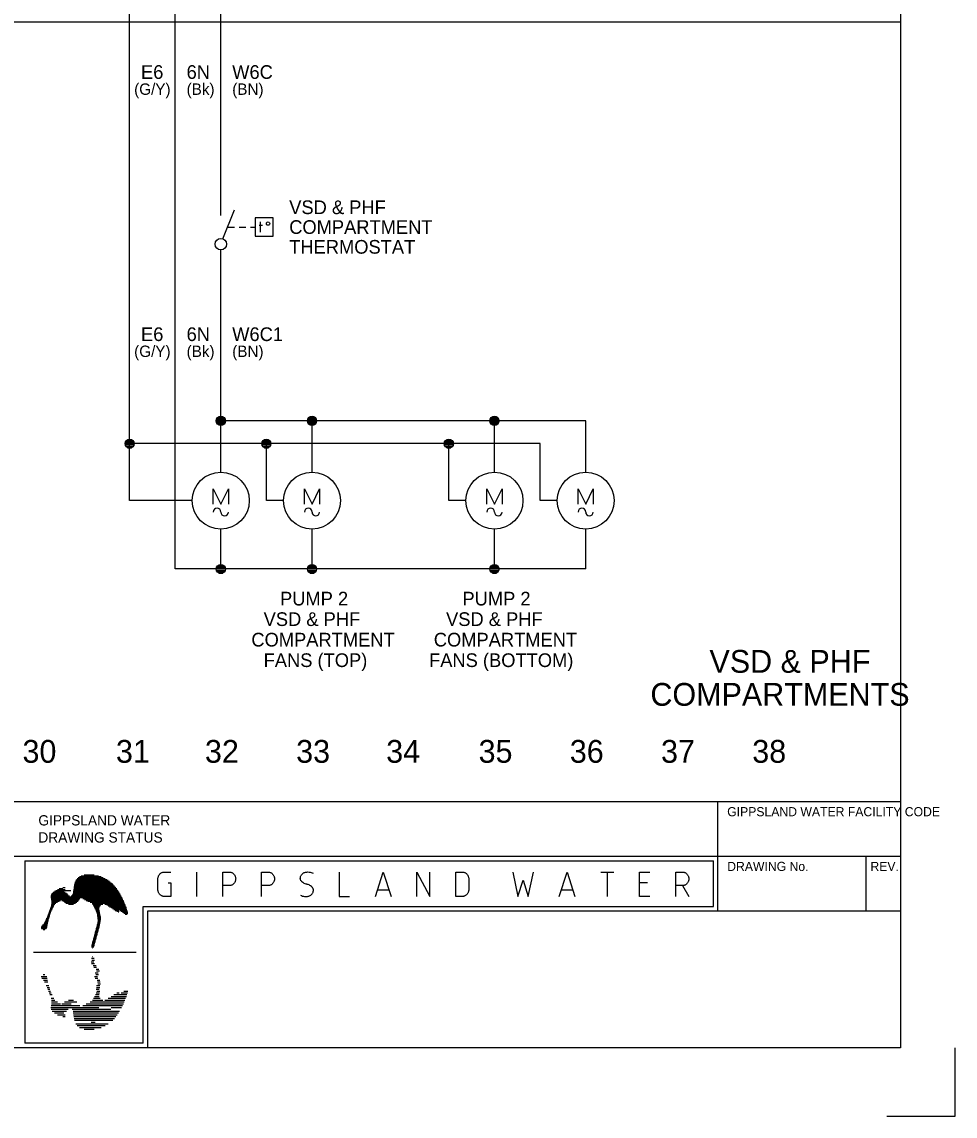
# Model space of a CAD drawing. Extents: x 0 to 841, y 0 to 594.
# Drawn here: x 636.4 to 841, y 0 to 240 of the extents above; entities that cross this region are included whole.
import ezdxf

# ---------------------------------------------------------------- set-up
doc = ezdxf.new("R2010")
doc.units = 0
for name, color, linetype in [('A1BORDER', 7, 'Continuous'), ('Level 1', 7, 'Continuous'), ('Level 10', 7, 'Continuous')]:
    doc.layers.add(name, color=color, linetype=linetype)

msp = doc.modelspace()

# ---------------------------------------------------------------- linework, layer by layer
at = {"layer": 'A1BORDER'}
for p, q in [((829, 581), (829, 15)), ((592.5, 69), (829, 69)), ((789, 45), (789, 69)), ((28, 57), (829, 57)), ((637, 56), (788, 56)), ((637, 56), (637, 16)), ((788, 46), (788, 56)), ((821.5, 45), (821.5, 57)), ((650.01, 52.92), (652.2, 52.92)), ((647.85, 50.52), (656.69, 50.52)), ((647.88, 50.72), (656.5, 50.72)), ((647.91, 50.92), (656.3, 50.92)), ((647.96, 51.12), (656.08, 51.12)), ((648.03, 51.32), (655.85, 51.32)), ((648.12, 51.52), (655.59, 51.52)), ((648.23, 51.72), (655.31, 51.72)), ((648.37, 51.92), (655, 51.92)), ((648.53, 52.12), (654.64, 52.12)), ((648.74, 52.32), (654.24, 52.32)), ((649.02, 52.52), (653.76, 52.52)), ((649.39, 52.72), (653.15, 52.72)), ((642.73, 48.12), (658.25, 48.12)), ((642.75, 48.32), (646.79, 48.32)), ((642.81, 48.52), (646.55, 48.52)), ((642.9, 48.72), (646.37, 48.72)), ((643.04, 48.92), (646.16, 48.92)), ((643.26, 49.12), (645.9, 49.12)), ((643.54, 49.32), (645.57, 49.32)), ((643.85, 49.52), (647.09, 49.52)), ((644.18, 49.72), (645.89, 49.72)), ((644.54, 49.92), (645.36, 49.92)), ((645.37, 50.12), (645.86, 50.12)), ((647.19, 48.32), (658.14, 48.32)), ((647.42, 48.52), (658.03, 48.52)), ((647.54, 48.72), (657.92, 48.72)), ((647.61, 48.92), (657.8, 48.92)), ((647.63, 49.12), (657.68, 49.12)), ((647.66, 49.32), (657.57, 49.32)), ((647.69, 49.52), (657.44, 49.52)), ((647.71, 49.72), (657.31, 49.72)), ((647.75, 49.92), (657.17, 49.92)), ((647.78, 50.12), (657.02, 50.12)), ((647.81, 50.32), (656.86, 50.32)), ((642.65, 45.72), (643.2, 45.72)), ((642.72, 45.92), (643.3, 45.92)), ((642.74, 47.92), (658.35, 47.92)), ((642.79, 47.72), (649.08, 47.72)), ((642.79, 46.12), (643.4, 46.12)), ((642.83, 47.52), (648.95, 47.52)), ((642.84, 46.32), (643.5, 46.32)), ((642.85, 47.31), (644.88, 47.31)), ((642.87, 47.12), (644.57, 47.12)), ((642.87, 46.52), (643.6, 46.52)), ((642.88, 46.92), (644.23, 46.92)), ((642.88, 46.72), (643.83, 46.72)), ((645.14, 47.31), (648.83, 47.31)), ((645.49, 47.12), (648.67, 47.12)), ((645.76, 46.92), (648.42, 46.92)), ((646.05, 46.72), (648.11, 46.72)), ((646.62, 46.52), (647.67, 46.52)), ((649.72, 47.72), (658.45, 47.72)), ((650.12, 47.52), (658.55, 47.52)), ((650.48, 47.31), (658.64, 47.31)), ((650.87, 47.12), (658.73, 47.12)), ((651.36, 46.92), (658.82, 46.92)), ((651.76, 46.72), (658.9, 46.72)), ((651.88, 46.52), (654.15, 46.52)), ((651.99, 46.32), (653.71, 46.32)), ((652.1, 46.12), (653.52, 46.12)), ((652.2, 45.92), (653.4, 45.92)), ((652.31, 45.72), (653.33, 45.72)), ((654.57, 46.52), (658.99, 46.52)), ((655, 46.32), (659.07, 46.32)), ((655.31, 46.12), (659.14, 46.12)), ((655.62, 45.92), (659.22, 45.92)), ((655.93, 45.72), (659.29, 45.72)), ((663, 46), (788, 46)), ((663, 16), (663, 46)), ((641.73, 43.32), (642.3, 43.32)), ((641.82, 43.51), (642.35, 43.51)), ((641.91, 43.72), (642.41, 43.72)), ((641.99, 43.92), (642.48, 43.92)), ((642.06, 44.12), (642.55, 44.12)), ((642.13, 44.32), (642.62, 44.32)), ((642.21, 44.52), (642.69, 44.52)), ((642.28, 44.72), (642.76, 44.72)), ((642.35, 44.92), (642.83, 44.92)), ((642.43, 45.12), (642.9, 45.12)), ((642.5, 45.32), (643, 45.32)), ((642.57, 45.52), (643.1, 45.52)), ((652.41, 45.52), (653.31, 45.52)), ((652.5, 45.32), (653.34, 45.32)), ((652.6, 45.12), (653.38, 45.12)), ((652.69, 44.92), (653.41, 44.92)), ((652.78, 44.72), (653.44, 44.72)), ((652.83, 44.52), (653.48, 44.52)), ((652.86, 44.32), (653.53, 44.32)), ((652.89, 44.12), (653.57, 44.12)), ((652.91, 43.92), (653.62, 43.92)), ((652.94, 43.72), (653.67, 43.72)), ((652.97, 43.51), (653.71, 43.51)), ((653, 43.32), (653.69, 43.32)), ((656.24, 45.52), (659.35, 45.52)), ((656.55, 45.32), (659.42, 45.32)), ((656.86, 45.12), (657.74, 45.12)), ((657.17, 44.92), (657.68, 44.92)), ((657.51, 44.72), (657.54, 44.72)), ((657.91, 45.12), (659.48, 45.12)), ((658.19, 44.92), (659.54, 44.92)), ((658.47, 44.72), (659.59, 44.72)), ((658.75, 44.52), (659.58, 44.52)), ((659.02, 44.32), (659.47, 44.32)), ((664, 45), (829, 45)), ((664, 15), (664, 45)), ((640.62, 41.32), (641.88, 41.32)), ((640.63, 41.52), (641.93, 41.52)), ((640.72, 41.12), (641.73, 41.12)), ((640.73, 41.72), (641.95, 41.72)), ((640.9, 41.92), (641.97, 41.92)), ((641.03, 40.92), (641.43, 40.92)), ((641.1, 42.12), (642, 42.12)), ((641.25, 42.31), (642.04, 42.31)), ((641.37, 42.52), (642.09, 42.52)), ((641.46, 42.72), (642.15, 42.72)), ((641.55, 42.92), (642.2, 42.92)), ((641.64, 43.12), (642.25, 43.12)), ((652.57, 40.92), (653.2, 40.92)), ((652.63, 41.12), (653.26, 41.12)), ((652.68, 41.32), (653.31, 41.32)), ((652.74, 41.52), (653.37, 41.52)), ((652.79, 41.72), (653.41, 41.72)), ((652.85, 41.92), (653.45, 41.92)), ((652.9, 42.12), (653.49, 42.12)), ((652.95, 42.31), (653.53, 42.31)), ((652.99, 42.52), (653.57, 42.52)), ((653.02, 43.12), (653.67, 43.12)), ((653.03, 42.72), (653.61, 42.72)), ((653.05, 42.92), (653.64, 42.92)), ((651.92, 38.52), (652.55, 38.52)), ((651.98, 38.72), (652.61, 38.72)), ((652.03, 38.92), (652.66, 38.92)), ((652.09, 39.12), (652.72, 39.12)), ((652.14, 39.32), (652.77, 39.32)), ((652.2, 39.52), (652.82, 39.52)), ((652.25, 39.72), (652.88, 39.72)), ((652.3, 39.92), (652.93, 39.92)), ((652.36, 40.12), (652.99, 40.12)), ((652.41, 40.32), (653.04, 40.32)), ((652.47, 40.52), (653.1, 40.52)), ((652.52, 40.72), (653.15, 40.72)), ((651.63, 37.32), (652.23, 37.32)), ((651.64, 37.12), (652.17, 37.12)), ((651.65, 37.52), (652.28, 37.52)), ((651.71, 37.72), (652.34, 37.72)), ((651.76, 37.92), (652.39, 37.92)), ((651.79, 36.92), (651.9, 36.92)), ((651.82, 38.12), (652.44, 38.12)), ((651.87, 38.32), (652.5, 38.32)), ((638.93, 35.98), (661.47, 35.98)), ((651.54, 33.84), (652.17, 33.84)), ((651.63, 34.64), (652.23, 34.64)), ((651.71, 34.24), (652.34, 34.24)), ((651.79, 35.04), (651.9, 35.04)), ((651.65, 33.44), (652.28, 33.44)), ((652.03, 33.04), (652.66, 33.04)), ((652.14, 32.64), (652.77, 32.64)), ((652.47, 31.44), (653.1, 31.44)), ((652.66, 32.24), (653.29, 32.24)), ((652.77, 31.84), (653.4, 31.84)), ((640.62, 30.64), (641.88, 30.64)), ((640.73, 30.24), (641.95, 30.24)), ((641.03, 31.04), (641.43, 31.04)), ((641.1, 29.84), (642, 29.84)), ((641.37, 29.44), (642.09, 29.44)), ((652.34, 30.64), (652.97, 30.64)), ((652.45, 30.24), (653.07, 30.24)), ((652.57, 31.04), (653.2, 31.04)), ((652.9, 29.84), (653.49, 29.84)), ((652.99, 29.44), (653.57, 29.44)), ((653.05, 29.04), (653.64, 29.04)), ((641.73, 28.64), (642.3, 28.64)), ((641.91, 28.24), (642.41, 28.24)), ((642.06, 27.84), (642.55, 27.84)), ((642.21, 27.44), (642.69, 27.44)), ((642.35, 27.04), (642.83, 27.04)), ((642.5, 26.64), (643, 26.64)), ((652.5, 26.64), (653.34, 26.64)), ((652.66, 27.84), (653.35, 27.84)), ((652.69, 27.04), (653.41, 27.04)), ((652.72, 28.24), (653.44, 28.24)), ((652.77, 28.64), (653.46, 28.64)), ((652.83, 27.44), (653.48, 27.44)), ((656.55, 26.64), (659.42, 26.64)), ((657.17, 27.04), (657.68, 27.04)), ((658.19, 27.04), (659.54, 27.04)), ((658.75, 27.44), (659.58, 27.44)), ((642.79, 25.84), (643.4, 25.84)), ((642.79, 24.24), (649.08, 24.24)), ((642.85, 24.65), (644.88, 24.65)), ((642.87, 25.44), (643.6, 25.44)), ((642.88, 25.04), (644.23, 25.04)), ((645.14, 24.65), (647.18, 24.65)), ((645.76, 25.04), (648.42, 25.04)), ((646.62, 25.44), (647.67, 25.44)), ((649.72, 24.24), (658.45, 24.24)), ((650.48, 24.65), (658.64, 24.65)), ((651.36, 25.04), (658.82, 25.04)), ((651.88, 25.44), (654.15, 25.44)), ((652.1, 25.84), (653.52, 25.84)), ((652.31, 26.24), (653.33, 26.24)), ((654.57, 25.44), (658.99, 25.44)), ((655.31, 25.84), (659.14, 25.84)), ((655.93, 26.24), (659.29, 26.24)), ((642.73, 23.84), (653.27, 23.84)), ((642.81, 23.44), (646.55, 23.44)), ((643.04, 23.04), (646.16, 23.04)), ((643.54, 22.64), (645.57, 22.64)), ((644.18, 22.24), (645.89, 22.24)), ((645.37, 21.84), (645.86, 21.84)), ((647.42, 23.44), (655.89, 23.44)), ((647.61, 23.04), (657.8, 23.04)), ((647.66, 22.64), (657.57, 22.64)), ((647.71, 22.24), (657.31, 22.24)), ((647.78, 21.84), (657.02, 21.84)), ((655.94, 23.84), (658.25, 23.84)), ((647.85, 21.44), (656.69, 21.44)), ((647.91, 21.04), (656.3, 21.04)), ((648.23, 20.24), (655.31, 20.24)), ((648.53, 19.84), (654.64, 19.84)), ((649.02, 19.44), (653.76, 19.44)), ((651.57, 20.64), (652.44, 20.64)), ((650.01, 19.04), (652.2, 19.04)), ((829, 15), (28, 15)), ((663, 16), (637, 16)), ((829, 15), (829, 15)), ((841, 0), (841, 15)), ((826, 0), (841, 0))]:
    msp.add_line(p, q, dxfattribs=at)
for points in [[(668.49, 51.15), (669.06, 51.15), (669.06, 48.16), (667.64, 48.16), (667.51, 48.16), (667.39, 48.18), (667.28, 48.21), (667.15, 48.25), (667.04, 48.3), (666.93, 48.36), (666.82, 48.43), (666.73, 48.51), (666.64, 48.6), (666.55, 48.7), (666.48, 48.8), (666.41, 48.91), (666.35, 49.02), (666.31, 49.14), (666.27, 49.27), (666.24, 49.39), (666.22, 49.52), (666.22, 49.66), (666.22, 52.05), (666.22, 52.18), (666.24, 52.31), (666.27, 52.43), (666.31, 52.56), (666.35, 52.67), (666.41, 52.79), (666.48, 52.9), (666.55, 53), (666.64, 53.1), (666.73, 53.19), (666.82, 53.27), (666.93, 53.34), (667.04, 53.4), (667.15, 53.45), (667.28, 53.49), (667.39, 53.52), (667.51, 53.54), (667.64, 53.54), (669.06, 53.54)], [(674.74, 48.16), (674.74, 53.54)], [(680.42, 48.16), (680.42, 53.54), (681.84, 53.54), (681.96, 53.54), (682.08, 53.52), (682.2, 53.49), (682.32, 53.45), (682.43, 53.4), (682.54, 53.34), (682.65, 53.27), (682.74, 53.19), (682.84, 53.1), (682.92, 53), (682.99, 52.9), (683.06, 52.79), (683.12, 52.67), (683.17, 52.56), (683.21, 52.43), (683.23, 52.31), (683.25, 52.18), (683.26, 52.05), (683.25, 51.91), (683.23, 51.78), (683.21, 51.66), (683.17, 51.53), (683.12, 51.42), (683.06, 51.3), (682.99, 51.19), (682.92, 51.09), (682.84, 50.99), (682.74, 50.9), (682.65, 50.82), (682.54, 50.75), (682.43, 50.69), (682.32, 50.64), (682.2, 50.6), (682.08, 50.57), (681.96, 50.55), (681.84, 50.55), (680.42, 50.55)], [(688.93, 48.16), (688.93, 53.54), (690.35, 53.54), (690.47, 53.54), (690.59, 53.52), (690.71, 53.49), (690.83, 53.45), (690.94, 53.4), (691.05, 53.34), (691.16, 53.27), (691.26, 53.19), (691.35, 53.1), (691.43, 53), (691.51, 52.9), (691.57, 52.79), (691.63, 52.67), (691.68, 52.56), (691.72, 52.43), (691.75, 52.31), (691.76, 52.18), (691.77, 52.05), (691.76, 51.91), (691.75, 51.78), (691.72, 51.66), (691.68, 51.53), (691.63, 51.42), (691.57, 51.3), (691.51, 51.19), (691.43, 51.09), (691.35, 50.99), (691.26, 50.9), (691.16, 50.82), (691.05, 50.75), (690.94, 50.69), (690.83, 50.64), (690.71, 50.6), (690.59, 50.57), (690.47, 50.55), (690.35, 50.55), (688.93, 50.55)], [(697.45, 48.46), (697.67, 48.36), (697.9, 48.27), (698.12, 48.21), (698.36, 48.17), (698.6, 48.16), (698.84, 48.16), (698.87, 48.16), (699.03, 48.18), (699.18, 48.21), (699.33, 48.26), (699.48, 48.32), (699.62, 48.4), (699.72, 48.46), (699.81, 48.53), (699.9, 48.61), (699.98, 48.69), (700.05, 48.78), (700.11, 48.88), (700.17, 48.99), (700.22, 49.09), (700.25, 49.21), (700.28, 49.32), (700.29, 49.36), (700.3, 49.44), (700.3, 49.52), (700.3, 49.61), (700.29, 49.69), (700.27, 49.77), (700.25, 49.86), (700.22, 49.93), (700.18, 50.01), (700.14, 50.09), (700.09, 50.15), (700.04, 50.21), (700.01, 50.25), (699.85, 50.39), (699.69, 50.51), (699.52, 50.61), (699.34, 50.7), (699.15, 50.78), (698.95, 50.83), (698.87, 50.85), (698.68, 50.9), (698.49, 50.96), (698.3, 51.04), (698.12, 51.14), (697.96, 51.26), (697.8, 51.39), (697.73, 51.45), (697.67, 51.51), (697.62, 51.57), (697.58, 51.64), (697.53, 51.71), (697.5, 51.79), (697.47, 51.87), (697.46, 51.95), (697.44, 52.04), (697.43, 52.12), (697.43, 52.21), (697.44, 52.29), (697.45, 52.35), (697.47, 52.46), (697.51, 52.58), (697.55, 52.69), (697.61, 52.79), (697.67, 52.89), (697.74, 52.99), (697.82, 53.07), (697.9, 53.15), (697.99, 53.23), (698.02, 53.24), (698.15, 53.33), (698.3, 53.4), (698.44, 53.45), (698.6, 53.5), (698.75, 53.52), (698.87, 53.54), (699.11, 53.55), (699.35, 53.53), (699.58, 53.49), (699.82, 53.43), (700.04, 53.35), (700.27, 53.25)], [(705.96, 53.54), (705.96, 48.16), (708.23, 48.16)], [(713.91, 48.16), (715.61, 53.54), (717.32, 48.16)], [(722.99, 48.16), (722.99, 53.54), (725.83, 48.16), (725.83, 53.54)], [(731.52, 48.16), (731.52, 53.54), (732.94, 53.54), (733.06, 53.54), (733.18, 53.52), (733.3, 53.49), (733.42, 53.45), (733.53, 53.4), (733.64, 53.34), (733.75, 53.27), (733.84, 53.19), (733.94, 53.1), (734.02, 53), (734.09, 52.9), (734.16, 52.79), (734.22, 52.67), (734.27, 52.56), (734.31, 52.43), (734.33, 52.31), (734.35, 52.18), (734.36, 52.05), (734.36, 49.66), (734.35, 49.52), (734.33, 49.39), (734.31, 49.27), (734.27, 49.14), (734.22, 49.02), (734.16, 48.91), (734.09, 48.8), (734.02, 48.7), (733.94, 48.6), (733.84, 48.51), (733.75, 48.43), (733.64, 48.36), (733.53, 48.3), (733.42, 48.25), (733.3, 48.21), (733.18, 48.18), (733.06, 48.16), (732.94, 48.16), (731.52, 48.16)], [(744.01, 53.54), (745.14, 48.16), (746.28, 51.75), (747.41, 48.16), (748.55, 53.54)], [(754.22, 48.16), (755.92, 53.54), (757.63, 48.16)], [(763.31, 53.54), (766.15, 53.54)], [(764.73, 53.54), (764.73, 48.16)], [(774.09, 48.16), (771.82, 48.16), (771.82, 53.54), (774.09, 53.54)], [(779.78, 48.16), (779.78, 53.54), (781.2, 53.54), (781.32, 53.54), (781.44, 53.52), (781.56, 53.49), (781.68, 53.45), (781.79, 53.4), (781.9, 53.34), (782.01, 53.27), (782.1, 53.19), (782.2, 53.1), (782.28, 53), (782.35, 52.9), (782.42, 52.79), (782.48, 52.67), (782.53, 52.56), (782.56, 52.43), (782.59, 52.31), (782.61, 52.18), (782.61, 52.05), (782.61, 51.91), (782.59, 51.78), (782.56, 51.66), (782.53, 51.53), (782.48, 51.42), (782.42, 51.3), (782.35, 51.19), (782.28, 51.09), (782.2, 50.99), (782.1, 50.9), (782.01, 50.82), (781.9, 50.75), (781.79, 50.69), (781.68, 50.64), (781.56, 50.6), (781.44, 50.57), (781.32, 50.55), (781.2, 50.55), (779.78, 50.55)], [(773.53, 51.15), (771.82, 51.15)], [(781.2, 50.55), (782.61, 48.16)], [(714.48, 49.66), (716.75, 49.66)], [(754.79, 49.66), (757.06, 49.66)]]:
    msp.add_lwpolyline(points, dxfattribs=at)
at = {"layer": 'Level 1'}
for p, q in [((680, 200), (680, 418.75)), ((670, 120), (670, 408.75)), ((660, 135), (660, 398.75)), ((28, 240), (829, 240)), ((680, 197.5), (680, 200)), ((680.46, 192.41), (683, 198.75)), ((681.5, 195), (683, 195)), ((684, 195), (685.5, 195)), ((686.5, 195), (687.5, 195)), ((680, 141.25), (680, 190)), ((760, 152.5), (680, 152.5)), ((700, 141.25), (700, 152.5)), ((740, 141.25), (740, 152.5)), ((760, 141.25), (760, 152.5)), ((750, 147.5), (660, 147.5)), ((690, 135), (690, 147.5)), ((730, 135), (730, 147.5)), ((750, 135), (750, 147.5)), ((673.75, 135), (660, 135)), ((693.75, 135), (690, 135)), ((733.75, 135), (730, 135)), ((753.75, 135), (750, 135)), ((680, 120), (680, 128.75)), ((700, 120), (700, 128.75)), ((740, 120), (740, 128.75)), ((760, 120), (760, 128.75)), ((760, 120), (670, 120))]:
    msp.add_line(p, q, dxfattribs=at)
msp.add_lwpolyline([(687.5, 193), (691.5, 193), (691.5, 197), (687.5, 197)], close=True, dxfattribs=at)
for points in [[(688.38, 195.38), (689.13, 195.38)], [(688.63, 196.13), (688.63, 193.87)], [(690.36, 195.38), (690.18, 195.42), (690.05, 195.56), (689.99, 195.76), (690.05, 195.94), (690.18, 196.07), (690.36, 196.13), (690.56, 196.07), (690.7, 195.94), (690.74, 195.76), (690.7, 195.56), (690.56, 195.42), (690.36, 195.38)]]:
    msp.add_lwpolyline(points, dxfattribs=at)
msp.add_circle((680, 191.25), 1.25, dxfattribs=at)
at = {"layer": 'Level 10'}
for p, q in [((679, 152.5), (680.99, 152.5)), ((679.05, 152.8), (680.95, 152.8)), ((679.05, 152.2), (680.95, 152.2)), ((679.2, 153.1), (680.8, 153.1)), ((679.2, 151.9), (680.8, 151.9)), ((679.56, 153.4), (680.44, 153.4)), ((679.56, 151.6), (680.44, 151.6)), ((680, 153.5), (680, 153.5)), ((699, 152.5), (700.99, 152.5)), ((699.05, 152.8), (700.95, 152.8)), ((699.05, 152.2), (700.95, 152.2)), ((699.2, 153.1), (700.8, 153.1)), ((699.2, 151.9), (700.8, 151.9)), ((699.56, 153.4), (700.44, 153.4)), ((699.56, 151.6), (700.44, 151.6)), ((700, 153.5), (700, 153.5)), ((739, 152.5), (740.99, 152.5)), ((739.05, 152.8), (740.95, 152.8)), ((739.05, 152.2), (740.95, 152.2)), ((739.2, 153.1), (740.8, 153.1)), ((739.2, 151.9), (740.8, 151.9)), ((739.56, 153.4), (740.44, 153.4)), ((739.56, 151.6), (740.44, 151.6)), ((740, 153.5), (740, 153.5)), ((659, 147.5), (660.99, 147.5)), ((659.05, 147.8), (660.95, 147.8)), ((659.05, 147.2), (660.95, 147.2)), ((659.2, 148.1), (660.8, 148.1)), ((659.2, 146.9), (660.8, 146.9)), ((659.56, 148.4), (660.44, 148.4)), ((659.56, 146.6), (660.44, 146.6)), ((660, 148.5), (660, 148.5)), ((689, 147.5), (690.99, 147.5)), ((689.05, 147.8), (690.95, 147.8)), ((689.05, 147.2), (690.95, 147.2)), ((689.2, 148.1), (690.8, 148.1)), ((689.2, 146.9), (690.8, 146.9)), ((689.56, 148.4), (690.44, 148.4)), ((689.56, 146.6), (690.44, 146.6)), ((690, 148.5), (690, 148.5)), ((729, 147.5), (730.99, 147.5)), ((729.05, 147.8), (730.95, 147.8)), ((729.05, 147.2), (730.95, 147.2)), ((729.2, 148.1), (730.8, 148.1)), ((729.2, 146.9), (730.8, 146.9)), ((729.56, 148.4), (730.44, 148.4)), ((729.56, 146.6), (730.44, 146.6)), ((730, 148.5), (730, 148.5)), ((678.33, 137.58), (680, 134.25)), ((678.33, 134.25), (678.33, 137.58)), ((680, 134.25), (681.67, 137.58)), ((681.67, 137.58), (681.67, 134.25)), ((698.33, 137.58), (700, 134.25)), ((698.33, 134.25), (698.33, 137.58)), ((700, 134.25), (701.67, 137.58)), ((701.67, 137.58), (701.67, 134.25)), ((738.33, 137.58), (740, 134.25)), ((738.33, 134.25), (738.33, 137.58)), ((740, 134.25), (741.67, 137.58)), ((741.67, 137.58), (741.67, 134.25)), ((758.33, 137.58), (760, 134.25)), ((758.33, 134.25), (758.33, 137.58)), ((760, 134.25), (761.67, 137.58)), ((761.67, 137.58), (761.67, 134.25)), ((679.05, 120.3), (680.95, 120.3)), ((679.2, 120.6), (680.8, 120.6)), ((679.56, 120.9), (680.44, 120.9)), ((680, 121), (680, 121)), ((699.05, 120.3), (700.95, 120.3)), ((699.2, 120.6), (700.8, 120.6)), ((699.56, 120.9), (700.44, 120.9)), ((700, 121), (700, 121)), ((739.05, 120.3), (740.95, 120.3)), ((739.2, 120.6), (740.8, 120.6)), ((739.56, 120.9), (740.44, 120.9)), ((740, 121), (740, 121)), ((679, 120), (680.99, 120)), ((679.05, 119.7), (680.95, 119.7)), ((679.2, 119.4), (680.8, 119.4)), ((679.56, 119.1), (680.44, 119.1)), ((699, 120), (700.99, 120)), ((699.05, 119.7), (700.95, 119.7)), ((699.2, 119.4), (700.8, 119.4)), ((699.56, 119.1), (700.44, 119.1)), ((739, 120), (740.99, 120)), ((739.05, 119.7), (740.95, 119.7)), ((739.2, 119.4), (740.8, 119.4)), ((739.56, 119.1), (740.44, 119.1))]:
    msp.add_line(p, q, dxfattribs=at)
for centre, radius in [((680, 152.5), 1), ((700, 152.5), 1), ((740, 152.5), 1), ((660, 147.5), 1), ((690, 147.5), 1), ((730, 147.5), 1), ((680, 135), 6.25), ((700, 135), 6.25), ((740, 135), 6.25), ((760, 135), 6.25), ((680, 120), 1), ((700, 120), 1), ((740, 120), 1)]:
    msp.add_circle(centre, radius, dxfattribs=at)
for centre, start, end in [((679.17, 132.5), 0, 180), ((680.83, 132.5), 180, 0), ((699.17, 132.5), 0, 180), ((700.83, 132.5), 180, 0), ((739.17, 132.5), 0, 180), ((740.83, 132.5), 180, 0), ((759.17, 132.5), 0, 180), ((760.83, 132.5), 180, 0)]:
    msp.add_arc(centre, 0.83, start, end, dxfattribs=at)

# ---------------------------------------------------------------- texts
at = {"layer": 'A1BORDER'}
for s, height, p in [('GIPPSLAND WATER FACILITY CODE', 2, (791.03, 65.77)), ('GIPPSLAND WATER', 2.25, (640, 63.75)), ('DRAWING STATUS', 2.25, (640, 60)), ('DRAWING No.', 2, (791.03, 53.77)), ('REV.', 2, (822.43, 53.77))]:
    msp.add_text(s, height=height, dxfattribs=at).set_placement(p)
at = {"layer": 'Level 1'}
for s, height, p in [('E6', 3, (662.5, 227.5)), ('6N', 3, (672.5, 227.5)), ('W6C', 3, (682.5, 227.5)), ('(G/Y)', 2.5, (661, 224)), ('(Bk)', 2.5, (672.5, 224)), ('(BN)', 2.5, (682.5, 224)), ('VSD & PHF', 3, (695, 197.84)), ('COMPARTMENT', 3, (695, 193.5)), ('THERMOSTAT', 3, (695, 189.16)), ('E6', 3, (662.5, 170)), ('6N', 3, (672.5, 170)), ('W6C1', 3, (682.5, 170)), ('(G/Y)', 2.5, (661, 166.5)), ('(Bk)', 2.5, (672.5, 166.5)), ('(BN)', 2.5, (682.5, 166.5)), ('PUMP 2', 3, (692.98, 112)), ('PUMP 2', 3, (732.98, 112)), ('VSD & PHF', 3, (689.39, 107.5)), ('VSD & PHF', 3, (729.39, 107.5)), ('COMPARTMENT', 3, (686.7, 103)), ('COMPARTMENT', 3, (726.7, 103)), ('FANS (TOP)', 3, (689.39, 98.5)), ('FANS (BOTTOM)', 3, (725.66, 98.5)), ('VSD & PHF', 5, (787.14, 97.24)), ('COMPARTMENTS', 5, (774.19, 90)), ('30', 5, (636.52, 77.5)), ('31', 5, (657.01, 77.5)), ('32', 5, (676.52, 77.5)), ('33', 5, (696.52, 77.5)), ('34', 5, (716.26, 77.5)), ('35', 5, (736.52, 77.5)), ('36', 5, (756.52, 77.5)), ('37', 5, (776.52, 77.5)), ('38', 5, (796.52, 77.5))]:
    msp.add_text(s, height=height, dxfattribs=at).set_placement(p)

doc.saveas('drawing.dxf')
